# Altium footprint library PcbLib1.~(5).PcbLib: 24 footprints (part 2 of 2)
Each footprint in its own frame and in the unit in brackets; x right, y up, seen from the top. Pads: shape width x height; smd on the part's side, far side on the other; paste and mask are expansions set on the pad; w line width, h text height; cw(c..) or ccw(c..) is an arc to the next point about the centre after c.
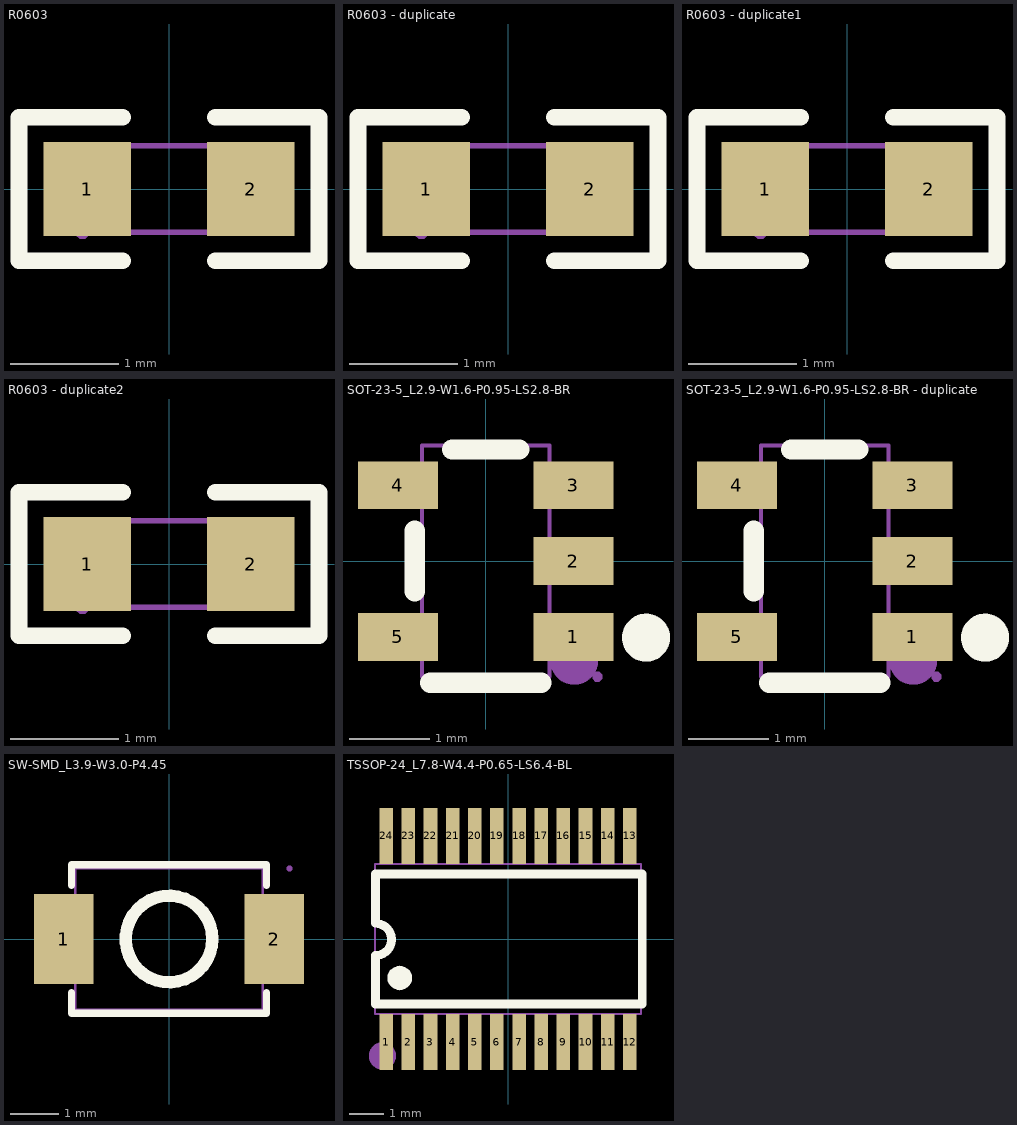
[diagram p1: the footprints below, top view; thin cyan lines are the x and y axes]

## R0603 [mm]
pads (2):
  rect 0.806x0.864 smd paste-100 mask+0.051: 1(-0.753,0) 2(0.753,0)
Top Overlay:
  lines w0.152: -0.426,-0.661 -1.385,-0.661 -1.385,0.661 -0.426,0.661 ; 0.426,-0.661 1.385,-0.661 1.385,0.661 0.426,0.661
Top Paste:
  region: 1.195,0.45 0.395,0.45 0.345,0.4 0.345,0.172 0.715,0.172 0.715,-0.158 0.345,-0.158 0.345,-0.4 0.395,-0.45 1.195,-0.45 1.245,-0.4 1.245,0.4
  region: -1.195,-0.45 -0.395,-0.45 -0.345,-0.4 -0.345,-0.172 -0.715,-0.172 -0.715,0.158 -0.345,0.158 -0.345,0.4 -0.395,0.45 -1.195,0.45 -1.245,0.4 -1.245,-0.4
Mechanical 6:
  lines w0.051: -0.8,-0.4 -0.8,0.4 0.8,0.4 0.8,-0.4 -0.8,-0.4
Mechanical 8:
  region: -0.74,-0.4 -0.74,-0.425 -0.775,-0.46 -0.825,-0.46 -0.86,-0.425 -0.86,-0.4 -0.86,-0.375 -0.825,-0.34 -0.775,-0.34 -0.74,-0.375 -0.74,-0.4
Mechanical 9:
  region: -0.8,-0.4 -0.8,0.4 -0.5,0.4 -0.5,-0.4
  region: 0.8,-0.4 0.8,0.4 0.5,0.4 0.5,-0.4

## R0603 - duplicate [mm]
pads (2):
  rect 0.806x0.864 smd paste-100 mask+0.051: 1(-0.753,0) 2(0.753,0)
Top Overlay:
  lines w0.152: -0.426,-0.661 -1.385,-0.661 -1.385,0.661 -0.426,0.661 ; 0.426,-0.661 1.385,-0.661 1.385,0.661 0.426,0.661
Top Paste:
  region: 1.195,0.45 0.395,0.45 0.345,0.4 0.345,0.172 0.715,0.172 0.715,-0.158 0.345,-0.158 0.345,-0.4 0.395,-0.45 1.195,-0.45 1.245,-0.4 1.245,0.4
  region: -1.195,-0.45 -0.395,-0.45 -0.345,-0.4 -0.345,-0.172 -0.715,-0.172 -0.715,0.158 -0.345,0.158 -0.345,0.4 -0.395,0.45 -1.195,0.45 -1.245,0.4 -1.245,-0.4
Mechanical 6:
  lines w0.051: -0.8,-0.4 -0.8,0.4 0.8,0.4 0.8,-0.4 -0.8,-0.4
Mechanical 8:
  region: -0.74,-0.4 -0.74,-0.425 -0.775,-0.46 -0.825,-0.46 -0.86,-0.425 -0.86,-0.4 -0.86,-0.375 -0.825,-0.34 -0.775,-0.34 -0.74,-0.375 -0.74,-0.4
Mechanical 9:
  region: -0.8,-0.4 -0.8,0.4 -0.5,0.4 -0.5,-0.4
  region: 0.8,-0.4 0.8,0.4 0.5,0.4 0.5,-0.4

## R0603 - duplicate1 [mm]
pads (2):
  rect 0.806x0.864 smd paste-100 mask+0.051: 1(-0.753,0) 2(0.753,0)
Top Overlay:
  lines w0.152: -0.426,-0.661 -1.385,-0.661 -1.385,0.661 -0.426,0.661 ; 0.426,-0.661 1.385,-0.661 1.385,0.661 0.426,0.661
Top Paste:
  region: -1.195,-0.45 -0.395,-0.45 -0.345,-0.4 -0.345,-0.172 -0.715,-0.172 -0.715,0.158 -0.345,0.158 -0.345,0.4 -0.395,0.45 -1.195,0.45 -1.245,0.4 -1.245,-0.4
  region: 1.195,0.45 0.395,0.45 0.345,0.4 0.345,0.172 0.715,0.172 0.715,-0.158 0.345,-0.158 0.345,-0.4 0.395,-0.45 1.195,-0.45 1.245,-0.4 1.245,0.4
Mechanical 6:
  lines w0.051: -0.8,-0.4 0.8,-0.4 0.8,0.4 -0.8,0.4 -0.8,-0.4
Mechanical 8:
  region: -0.74,-0.4 -0.74,-0.425 -0.775,-0.46 -0.825,-0.46 -0.86,-0.425 -0.86,-0.4 -0.86,-0.375 -0.825,-0.34 -0.775,-0.34 -0.74,-0.375 -0.74,-0.4
Mechanical 9:
  region: 0.8,-0.4 0.8,0.4 0.5,0.4 0.5,-0.4
  region: -0.8,-0.4 -0.8,0.4 -0.5,0.4 -0.5,-0.4

## R0603 - duplicate2 [mm]
pads (2):
  rect 0.806x0.864 smd paste-100 mask+0.051: 1(-0.753,0) 2(0.753,0)
Top Overlay:
  lines w0.152: -0.426,-0.661 -1.385,-0.661 -1.385,0.661 -0.426,0.661 ; 0.426,-0.661 1.385,-0.661 1.385,0.661 0.426,0.661
Top Paste:
  region: 1.195,0.45 0.395,0.45 0.345,0.4 0.345,0.172 0.715,0.172 0.715,-0.158 0.345,-0.158 0.345,-0.4 0.395,-0.45 1.195,-0.45 1.245,-0.4 1.245,0.4
  region: -1.195,-0.45 -0.395,-0.45 -0.345,-0.4 -0.345,-0.172 -0.715,-0.172 -0.715,0.158 -0.345,0.158 -0.345,0.4 -0.395,0.45 -1.195,0.45 -1.245,0.4 -1.245,-0.4
Mechanical 6:
  lines w0.051: -0.8,-0.4 -0.8,0.4 0.8,0.4 0.8,-0.4 -0.8,-0.4
Mechanical 8:
  region: -0.74,-0.4 -0.74,-0.425 -0.775,-0.46 -0.825,-0.46 -0.86,-0.425 -0.86,-0.4 -0.86,-0.375 -0.825,-0.34 -0.775,-0.34 -0.74,-0.375 -0.74,-0.4
Mechanical 9:
  region: -0.8,-0.4 -0.8,0.4 -0.5,0.4 -0.5,-0.4
  region: 0.8,-0.4 0.8,0.4 0.5,0.4 0.5,-0.4

## SOT-23-5_L2.9-W1.6-P0.95-LS2.8-BR [mm]
pads (5):
  rect 1x0.6 smd paste+0 mask+0.05: 1(1.1,-0.95) 2(1.1,0) 3(1.1,0.95) 4(-1.1,0.95) 5(-1.1,-0.95)
Top Overlay:
  circle w0.3: c2.01,-0.96 r0.15
  lines w0.254: -0.889,-0.381 -0.889,0.381 ; -0.699,-1.524 0.698,-1.524 ; -0.422,1.397 0.422,1.397
Mechanical 2:
  circle w0.3: c1.11,-1.25 r0.15
Mechanical 6:
  lines w0.051: -0.8,-1.45 0.8,-1.45 0.8,1.45 -0.8,1.45 -0.8,-1.45
Mechanical 7:
  region: -0.79,-1.15 -0.96,-1.15 -0.96,-0.75 -0.79,-0.75
  region: -0.79,0.75 -0.96,0.75 -0.96,1.15 -0.79,1.15
  region: 0.96,-1.15 0.79,-1.15 0.79,-0.75 0.96,-0.75
  region: 0.96,0.75 0.79,0.75 0.79,1.15 0.96,1.15
  region: 0.96,-0.2 0.79,-0.2 0.79,0.2 0.96,0.2
Mechanical 8:
  region: 1.46,-1.45 1.46,-1.475 1.425,-1.51 1.375,-1.51 1.34,-1.475 1.34,-1.45 1.34,-1.425 1.375,-1.39 1.425,-1.39 1.46,-1.425 1.46,-1.45
Mechanical 9:
  region: -0.95,-1.15 -1.4,-1.15 -1.4,-0.75 -0.95,-0.75
  region: -0.95,0.75 -1.4,0.75 -1.4,1.15 -0.95,1.15
  region: 1.4,-1.15 0.95,-1.15 0.95,-0.75 1.4,-0.75
  region: 1.4,0.75 0.95,0.75 0.95,1.15 1.4,1.15
  region: 1.4,-0.2 0.95,-0.2 0.95,0.2 1.4,0.2

## SOT-23-5_L2.9-W1.6-P0.95-LS2.8-BR - duplicate [mm]
pads (5):
  rect 1x0.6 smd paste+0 mask+0.05: 1(1.1,-0.95) 2(1.1,0) 3(1.1,0.95) 4(-1.1,0.95) 5(-1.1,-0.95)
Top Overlay:
  circle w0.3: c2.01,-0.96 r0.15
  lines w0.254: -0.889,-0.381 -0.889,0.381 ; -0.699,-1.524 0.698,-1.524 ; -0.422,1.397 0.422,1.397
Mechanical 2:
  circle w0.3: c1.11,-1.25 r0.15
Mechanical 6:
  lines w0.051: -0.8,-1.45 0.8,-1.45 0.8,1.45 -0.8,1.45 -0.8,-1.45
Mechanical 7:
  region: -0.79,-1.15 -0.96,-1.15 -0.96,-0.75 -0.79,-0.75
  region: -0.79,0.75 -0.96,0.75 -0.96,1.15 -0.79,1.15
  region: 0.96,-1.15 0.79,-1.15 0.79,-0.75 0.96,-0.75
  region: 0.96,0.75 0.79,0.75 0.79,1.15 0.96,1.15
  region: 0.96,-0.2 0.79,-0.2 0.79,0.2 0.96,0.2
Mechanical 8:
  region: 1.46,-1.45 1.46,-1.475 1.425,-1.51 1.375,-1.51 1.34,-1.475 1.34,-1.45 1.34,-1.425 1.375,-1.39 1.425,-1.39 1.46,-1.425 1.46,-1.45
Mechanical 9:
  region: -0.95,-1.15 -1.4,-1.15 -1.4,-0.75 -0.95,-0.75
  region: -0.95,0.75 -1.4,0.75 -1.4,1.15 -0.95,1.15
  region: 1.4,-1.15 0.95,-1.15 0.95,-0.75 1.4,-0.75
  region: 1.4,0.75 0.95,0.75 0.95,1.15 1.4,1.15
  region: 1.4,-0.2 0.95,-0.2 0.95,0.2 1.4,0.2

## SW-SMD_L3.9-W3.0-P4.45 [mm]
pads (2):
  rect 1.23x1.86 smd: 1(-2.185,0) 2(2.185,0)
Top Overlay:
  circle w0.254: c0,0 r0.9
  lines w0.152: -2.026,-1.11 -2.026,-1.541 2.026,-1.541 2.026,-1.11 ; -2.026,1.11 -2.026,1.541 2.026,1.541 2.026,1.11
Mechanical 6:
  lines w0.051: -1.95,-1.465 -1.95,1.465 1.95,1.465 1.95,-1.465 -1.95,-1.465
Mechanical 8:
  region: 2.56,1.465 2.56,1.44 2.525,1.405 2.475,1.405 2.44,1.44 2.44,1.465 2.44,1.49 2.475,1.525 2.525,1.525 2.56,1.49 2.56,1.465
Mechanical 9:
  region: -2.5,0.65 -2.5,-0.65 -1.6,-0.65 -1.6,0.65
  region: 2.5,0.65 2.5,-0.65 1.6,-0.65 1.6,0.65

## TSSOP-24_L7.8-W4.4-P0.65-LS6.4-BL [mm]
pads (24):
  rect 0.4x1.65 smd: 1(-3.575,-3.023) 2(-2.925,-3.023) 3(-2.275,-3.023) 4(-1.625,-3.023) 5(-0.975,-3.023) 6(-0.325,-3.023) 7(0.325,-3.023) 8(0.975,-3.023) 9(1.625,-3.023) 10(2.275,-3.023) 11(2.925,-3.023) 12(3.575,-3.023) 13(3.575,3.023) 14(2.925,3.023) 15(2.275,3.023) 16(1.625,3.023) 17(0.975,3.023) 18(0.325,3.023) 19(-0.325,3.023) 20(-0.975,3.023) 21(-1.625,3.023) 22(-2.275,3.023) 23(-2.925,3.023) 24(-3.575,3.023)
Top Overlay:
  region: -3.529,-1.143 -3.52,-1.064 -3.494,-0.989 -3.452,-0.922 -3.396,-0.866 -3.329,-0.824 -3.254,-0.798 -3.175,-0.789 -3.096,-0.798 -3.021,-0.824 -2.954,-0.866 -2.898,-0.922 -2.856,-0.989 -2.83,-1.064 -2.821,-1.143 -2.83,-1.222 -2.856,-1.297 -2.898,-1.364 -2.954,-1.42 -3.021,-1.462 -3.096,-1.488 -3.175,-1.497 -3.254,-1.488 -3.329,-1.462 -3.396,-1.42 -3.452,-1.364 -3.494,-1.297 -3.52,-1.222
  lines w0.254: -3.886,0.457 cw(c-3.886,-0.013) -3.886,-0.483 -3.886,-1.753 -3.886,-1.905 3.937,-1.905 3.937,1.905 -3.886,1.905 -3.886,1.753 -3.886,0.483
Mechanical 2:
  circle w0.4: c-3.683,-3.429 r0.2
Mechanical 6:
  lines w0.051: -3.9,-2.2 3.9,-2.2 3.9,2.2 -3.9,2.2 -3.9,-2.2
Mechanical 7:
  region: -0.425,-2.588 -0.225,-2.588 -0.225,-2.188 -0.425,-2.188
  region: -1.075,-2.588 -0.875,-2.588 -0.875,-2.188 -1.075,-2.188
  region: -1.725,-2.588 -1.525,-2.588 -1.525,-2.188 -1.725,-2.188
  region: -2.375,-2.588 -2.175,-2.588 -2.175,-2.188 -2.375,-2.188
  region: -3.025,-2.588 -2.825,-2.588 -2.825,-2.188 -3.025,-2.188
  region: -3.675,-2.588 -3.475,-2.588 -3.475,-2.188 -3.675,-2.188
  region: 3.475,-2.588 3.675,-2.588 3.675,-2.188 3.475,-2.188
  region: 2.825,-2.588 3.025,-2.588 3.025,-2.188 2.825,-2.188
  region: 2.175,-2.588 2.375,-2.588 2.375,-2.188 2.175,-2.188
  region: 1.525,-2.588 1.725,-2.588 1.725,-2.188 1.525,-2.188
  region: 0.875,-2.588 1.075,-2.588 1.075,-2.188 0.875,-2.188
  region: 0.225,-2.588 0.425,-2.588 0.425,-2.188 0.225,-2.188
  region: 0.425,2.588 0.225,2.588 0.225,2.188 0.425,2.188
  region: 1.075,2.588 0.875,2.588 0.875,2.188 1.075,2.188
  region: 1.725,2.588 1.525,2.588 1.525,2.188 1.725,2.188
  region: 2.375,2.588 2.175,2.588 2.175,2.188 2.375,2.188
  region: 3.025,2.588 2.825,2.588 2.825,2.188 3.025,2.188
  region: 3.675,2.588 3.475,2.588 3.475,2.188 3.675,2.188
  region: -3.475,2.588 -3.675,2.588 -3.675,2.188 -3.475,2.188
  region: -2.825,2.588 -3.025,2.588 -3.025,2.188 -2.825,2.188
  region: -2.175,2.588 -2.375,2.588 -2.375,2.188 -2.175,2.188
  region: -1.525,2.588 -1.725,2.588 -1.725,2.188 -1.525,2.188
  region: -0.875,2.588 -1.075,2.588 -1.075,2.188 -0.875,2.188
  region: -0.225,2.588 -0.425,2.588 -0.425,2.188 -0.225,2.188
Mechanical 8:
  region: -3.84,-3.186 -3.84,-3.211 -3.875,-3.246 -3.925,-3.246 -3.96,-3.211 -3.96,-3.186 -3.96,-3.161 -3.925,-3.126 -3.875,-3.126 -3.84,-3.161 -3.84,-3.186
Mechanical 9:
  region: -0.425,-2.586 -0.225,-2.586 -0.225,-3.186 -0.425,-3.186
  region: -1.075,-2.586 -0.875,-2.586 -0.875,-3.186 -1.075,-3.186
  region: -1.725,-2.586 -1.525,-2.586 -1.525,-3.186 -1.725,-3.186
  region: -2.375,-2.586 -2.175,-2.586 -2.175,-3.186 -2.375,-3.186
  region: -3.025,-2.586 -2.825,-2.586 -2.825,-3.186 -3.025,-3.186
  region: -3.675,-2.586 -3.475,-2.586 -3.475,-3.186 -3.675,-3.186
  region: 3.475,-2.586 3.675,-2.586 3.675,-3.186 3.475,-3.186
  region: 2.825,-2.586 3.025,-2.586 3.025,-3.186 2.825,-3.186
  region: 2.175,-2.586 2.375,-2.586 2.375,-3.186 2.175,-3.186
  region: 1.525,-2.586 1.725,-2.586 1.725,-3.186 1.525,-3.186
  region: 0.875,-2.586 1.075,-2.586 1.075,-3.186 0.875,-3.186
  region: 0.225,-2.586 0.425,-2.586 0.425,-3.186 0.225,-3.186
  region: 0.425,2.586 0.225,2.586 0.225,3.186 0.425,3.186
  region: 1.075,2.586 0.875,2.586 0.875,3.186 1.075,3.186
  region: 1.725,2.586 1.525,2.586 1.525,3.186 1.725,3.186
  region: 2.375,2.586 2.175,2.586 2.175,3.186 2.375,3.186
  region: 3.025,2.586 2.825,2.586 2.825,3.186 3.025,3.186
  region: 3.675,2.586 3.475,2.586 3.475,3.186 3.675,3.186
  region: -3.475,2.586 -3.675,2.586 -3.675,3.186 -3.475,3.186
  region: -2.825,2.586 -3.025,2.586 -3.025,3.186 -2.825,3.186
  region: -2.175,2.586 -2.375,2.586 -2.375,3.186 -2.175,3.186
  region: -1.525,2.586 -1.725,2.586 -1.725,3.186 -1.525,3.186
  region: -0.875,2.586 -1.075,2.586 -1.075,3.186 -0.875,3.186
  region: -0.225,2.586 -0.425,2.586 -0.425,3.186 -0.225,3.186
